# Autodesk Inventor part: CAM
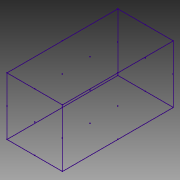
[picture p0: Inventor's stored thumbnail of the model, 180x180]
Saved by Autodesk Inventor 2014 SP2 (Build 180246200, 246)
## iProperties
Created: 2005-05
Part Number: CAM
Document SubType Name: Modeling
Designer: Administrator
Material: Allgemein
Density: 1 g/cm^3
Appearance: Vorgabe
Author: Administrator
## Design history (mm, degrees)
sketch "Rohmodell"
node "Volumenkörper"
node "Flächenkörper"
